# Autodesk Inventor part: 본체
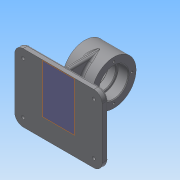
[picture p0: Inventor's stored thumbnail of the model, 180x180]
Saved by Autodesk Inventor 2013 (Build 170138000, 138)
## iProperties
Created: 2019-09
Part Number: 본체
Material: 일반
Document SubType Name: Modeling
Designer: Administrator
Density: 1 g/cm^3
Author: Administrator
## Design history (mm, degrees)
sketch "스케치1"
  geometry: C1 r 32 at (0, 0); 1 further point
  constraints: 1 centre point, 1 coincident
  dimensions: "d0" = 64 diameter of C1
extrude "돌출1" new body sketch "스케치1" stored distance "d1" = 42; taper "d2" = 0 deg
node "작업 평면3"
sketch "스케치2"
  geometry: L1 (63, -62)-(-63, -62); L2 (-63, -62)-(-63, 36); L3 (-63, 36)-(63, 36); L4 (63, 36)-(63, -62); 2 further points
  constraints: 8 end point, 2 parallel, 1 horizontal, 1 midpoint, 1 perpendicular, 1 vertical alignment
  dimensions: "d5" = 126 distance of L2.end L3.end; "d6" = 98 distance of L1.end L2.end; "d7" = 36 distance from line of point (0, 0) L3
extrude "돌출2" join sketch "스케치2" distance "d8" = 9; taper "d9" = 0 deg
sketch "스케치4"
  geometry: L1 (-4, 32)-(4, 32); L2 (4, 32)-(4, -32); L3 (4, -32)-(-4, -32); L4 (-4, -32)-(-4, 32); L5 (-4, 32)-(4, -32); L6 (4, 32)-(-4, -32); L7 (-17, 4)-(17, 4); L8 (17, 4)-(17, -4); L9 (17, -4)-(-17, -4); L10 (-17, -4)-(-17, 4); L11 (-17, 4)-(17, -4); L12 (17, 4)-(-17, -4); 1 further point
  constraints: 24 end point, 4 midpoint, 4 parallel, 2 horizontal, 2 perpendicular
  dimensions: "d24" = 8 distance of L2.end L3.end; "d25" = 64 distance of L1.end L2.end; "d26" = 34 distance of L8.end L9.end; "d27" = 8 distance of L7.end L8.end
extrude "돌출3" join sketch "스케치4" stored distance "d28" = 9; taper "d29" = 0 deg
hole "구멍1" diameter "d32" = 36; stored, may be unused: countersink angle "d36" = 90 deg, drill point angle "d38" = 0 deg; dims "d30" = 10, "d31" = 10, "d33" = 6, "d34" = 42, "d35" = 15, "d37" = 21
hole "구멍2" diameter "d41" = 36; stored, may be unused: countersink angle "d45" = 90 deg, drill point angle "d47" = 0 deg; dims "d39" = 10, "d40" = 10, "d42" = 6, "d43" = 42, "d44" = 15, "d46" = 21
sketch "스케치5" dims "d48" = 52
  geometry: C1 r 32 at (0, 0) reference; 2 further points
  constraints: 2 vertical alignment, 1 coincident, 2 other
hole "구멍3" sketch "스케치5" at (0, 26) diameter "d49" = 3.242; stored, may be unused: countersink angle "d53" = 90 deg, drill point angle "d55" = 118 deg; dims "d50" = 8, "d51" = 42, "d52" = 15, "d54" = 10
fillet "모깎기1" dims "d59" = 12
sketch "스케치6"
  geometry: A1 r 12 centre (-51, -24) between (-63, -24) and (-51, -36) reference; A2 r 12 centre (51, -24) between (51, -36) and (63, -24) reference; A3 r 12 centre (51, 50) between (63, 50) and (51, 62) reference; A4 r 12 centre (-51, 50) between (-51, 62) and (-63, 50) reference; 1 further point
hole "구멍4" sketch "스케치6" at (-51, 50), (-51, -24), (51, -24), (51, 50) diameter "d60" = 4.5; stored, may be unused: countersink angle "d64" = 90 deg, drill point angle "d66" = 118 deg; dims "d61" = 8, "d62" = 8, "d63" = 4.4, "d65" = 10
sketch "스케치7"
  geometry: L1 (63, -24)-(63, 50) reference; L2 (51, 62)-(-51, 62) reference; 2 further points
  constraints: 1 other
  dimensions: "d67" = 10 distance from line of L2 point (0, 52); "d68" = 63 distance from line of L1 point (0, 52)
feature "엠보싱1" sketch "스케치7" dims "d26" = 34, "d27" = 8, "d69" = 0.5, "d70" = 0
fillet "모깎기2" dims "d71" = 3
chamfer "모따기1" distance "d77" = 1; stored, may be unused: second distance "d78" = 2, angle "d79" = 45 deg
fillet "모깎기8" dims "d80" = 0.3
fillet "모깎기11" dims "d83" = 3
fillet "모깎기12" dims "d84" = 3
fillet "모깎기13" dims "d85" = 3
fillet "모깎기14" dims "d86" = 3
node "솔리드1"
pattern_circular "원형 패턴1" dims angle "d57" = 360 deg
mirror "대칭1"
other parameters: "d4" = -59
